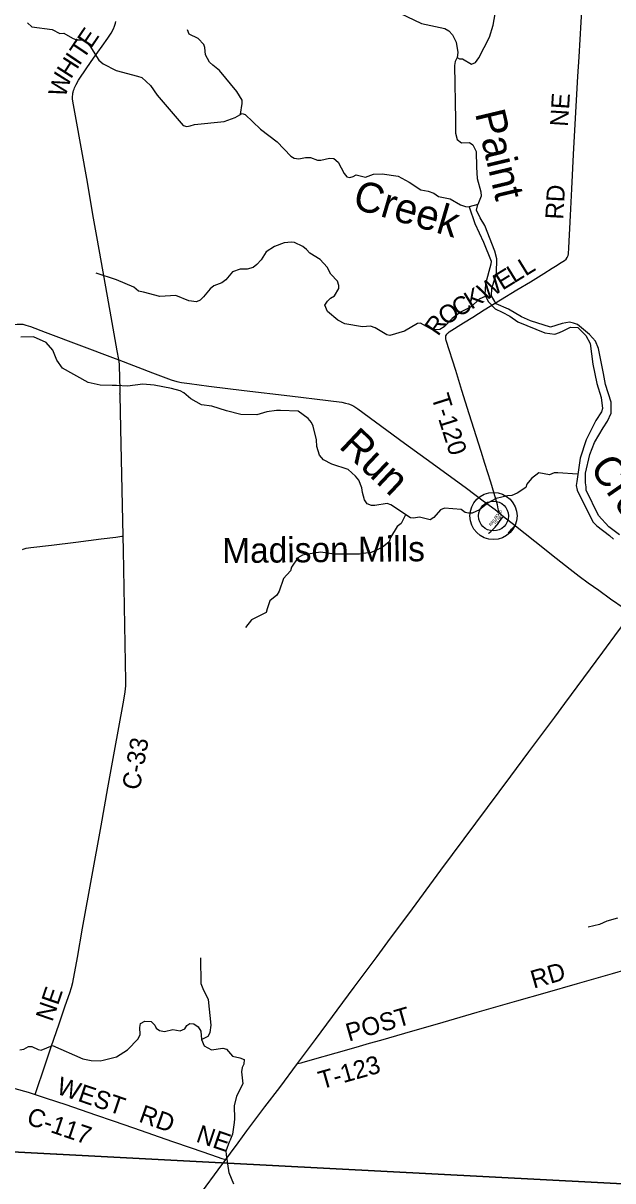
# Model space of a CAD drawing. Extents: x -51392 to 1635000, y 156707 to 696232.
# Drawn here: x 159089 to 168915, y 518358 to 537660 of the extents above; entities that cross this region are included whole.
import ezdxf

# ---------------------------------------------------------------- set-up
doc = ezdxf.new("R2010")
doc.units = 0
for name, color, linetype in [('GM_X_County_Road', 7, 'Continuous'), ('GM_X_County_Road_Text', 7, 'Continuous'), ('GM_X_Major_River', 7, 'Continuous'), ('GM_X_Major_River_Text', 7, 'Continuous'), ('GM_X_Minor_River', 7, 'Continuous'), ('GM_X_Minor_River_Text', 7, 'Continuous'), ('GM_X_Township', 7, 'Continuous'), ('GM_X_Township_Road', 7, 'Continuous'), ('GM_X_Township_Road_Text', 7, 'Continuous'), ('GM_X_Township_Subdivision', 7, 'Continuous'), ('GM_X_Township_Subdivision_Text', 7, 'Continuous'), ('GM_X_Unincorporated', 7, 'Continuous'), ('GM_X_Unincorporated_Text', 7, 'Continuous'), ('GM_X_US_Route', 7, 'Continuous')]:
    doc.layers.add(name, color=color, linetype=linetype)

msp = doc.modelspace()

# ---------------------------------------------------------------- linework, layer by layer
at = {"layer": 'GM_X_County_Road'}
for points in [[(160682, 532047), (160681, 532052), (160656, 532197), (160555, 532762), (160394, 533667), (160318, 534101), (160264, 534408), (160148, 535071), (159973, 536056), (159928, 536298), (159914, 536394), (159912, 536421), (159913, 536442), (159915, 536468), (159919, 536491), (159923, 536512), (159930, 536536), (159938, 536560), (159946, 536582), (159973, 536639), (160014, 536710), (160150, 536915), (160261, 537077), (160407, 537275), (160503, 537409), (160555, 537492), (160594, 537565), (160613, 537611), (160627, 537659), (160634, 537688)], [(157127, 532309), (157134, 532307), (157143, 532304), (157152, 532303), (157159, 532302), (157167, 532302), (157184, 532304), (157265, 532318), (157942, 532448), (158360, 532530), (158795, 532615), (158924, 532637), (158989, 532643), (159038, 532643), (159084, 532639), (159134, 532627), (159211, 532603), (159457, 532510), (160623, 532069), (160682, 532047)], [(160682, 532047), (161246, 531830), (161554, 531715), (161648, 531686), (161728, 531668), (161859, 531650), (162184, 531610), (162770, 531538), (163535, 531444), (164171, 531368), (164398, 531339), (164462, 531327), (164509, 531313), (164554, 531295), (164597, 531272), (164665, 531228), (165446, 530656), (165804, 530395), (166453, 529921), (166637, 529785), (166756, 529697), (166952, 529551), (167020, 529497)], [(160754, 529107), (160717, 530904), (160706, 531462), (160701, 531478), (160705, 531495), (160704, 531544), (160694, 531954), (160692, 531977), (160688, 532011), (160682, 532047)], [(167020, 529497), (167095, 529437)], [(167095, 529437), (167287, 529285)], [(167287, 529285), (167296, 529278), (167614, 529025), (167969, 528741), (168202, 528558), (168356, 528437), (168505, 528327), (168680, 528204), (168878, 528064), (169102, 527908), (169195, 527844), (169227, 527821)], [(159077, 528882), (159092, 528890), (159107, 528896), (159122, 528901), (159138, 528904), (159219, 528915), (159561, 528958), (159968, 529008), (160180, 529035), (160391, 529062), (160636, 529092), (160733, 529104), (160754, 529107)], [(159289, 519797), (159462, 520310), (159557, 520590), (159690, 520978), (159790, 521273), (159867, 521490), (159897, 521584), (159916, 521664), (159992, 522084), (160078, 522568), (160389, 524279), (160502, 524909), (160613, 525523), (160758, 526313), (160790, 526508), (160797, 526567), (160800, 526606), (160802, 526639), (160802, 526688), (160783, 527623), (160759, 528870), (160754, 529107)], [(157098, 519161), (157124, 519184), (157163, 519213), (157216, 519251), (157490, 519431), (157930, 519717), (158190, 519888), (158314, 519968), (158356, 519993), (158386, 520006), (158416, 520017), (158432, 520021), (158447, 520023), (158463, 520025), (158479, 520026), (158495, 520025), (158527, 520021), (158575, 520010), (158701, 519975), (158764, 519956), (158952, 519899), (159172, 519834), (159289, 519797)], [(159289, 519797), (159472, 519737), (159798, 519628), (160294, 519460), (160590, 519361), (160930, 519243), (161579, 519016), (161889, 518910), (162229, 518791), (162400, 518733), (162469, 518713)]]:
    msp.add_lwpolyline(points, dxfattribs=at)
at = {"layer": 'GM_X_Major_River'}
msp.add_line((166666, 534635), (166524, 534599), dxfattribs=at)
for points in [[(166320, 537089), (166361, 537065), (166411, 537067), (166559, 536979), (166627, 537007), (166683, 537083), (166862, 537424), (166924, 537625), (166981, 537970), (167129, 538419), (167129, 538501), (167079, 538678), (167029, 538810), (166997, 538983), (166955, 539631), (166957, 539697), (166958, 539996), (167046, 540558), (167107, 541279), (167185, 541590), (167233, 541794), (167287, 541921), (167466, 542164), (167534, 542314)], [(166320, 537089), (166286, 537019), (166278, 536957), (166296, 536042), (166292, 535825), (166320, 535721), (166392, 535663), (166526, 535668), (166583, 535630), (166637, 535522), (166643, 535261), (166652, 535071), (166715, 534850), (166721, 534776), (166666, 534635)], [(166524, 534599), (166616, 534320), (166762, 534011), (166886, 533692), (166884, 533640), (166792, 533315), (166782, 533137), (166838, 533020), (166956, 532898), (167073, 532840), (167197, 532777), (167331, 532681), (167784, 532498), (167951, 532476), (168027, 532504), (168089, 532530), (168210, 532590), (168332, 532586), (168466, 532454), (168538, 532317), (168584, 531972), (168648, 531653), (168722, 531420), (168742, 531234), (168728, 531180), (168630, 531037), (168471, 530712), (168371, 530406), (168313, 530016), (168303, 529950), (168321, 529874), (168583, 529348), (168651, 529278), (168858, 529120), (168924, 529055)], [(169026, 529129), (168848, 529260), (168679, 529453), (168469, 529872), (168471, 529932), (168461, 529998), (168459, 530155), (168535, 530468), (168608, 530666), (168754, 530915), (168829, 531025), (168887, 531156), (168889, 531340), (168793, 531637), (168759, 531820), (168679, 532235), (168627, 532357), (168524, 532470), (168328, 532636), (168260, 532660), (168194, 532673), (168071, 532655), (167877, 532592), (167542, 532699), (167395, 532761), (167179, 532890), (166970, 532982), (166892, 533116), (166898, 533237), (166979, 533490), (166981, 533730), (166951, 533861), (166784, 534284), (166702, 534413), (166644, 534541), (166666, 534635)]]:
    msp.add_lwpolyline(points, dxfattribs=at)
at = {"layer": 'GM_X_Minor_River'}
for points in [[(165366, 537828), (165729, 537655), (166114, 537569), (166182, 537535), (166244, 537468), (166305, 537342), (166331, 537169), (166320, 537089)], [(159163, 537664), (159233, 537600), (159572, 537552), (159700, 537487), (159767, 537491), (159909, 537409), (159979, 537385), (160081, 537381), (160136, 537351), (160200, 537285), (160348, 537042), (160420, 536984), (160641, 536873), (160996, 536777), (161066, 536752), (161214, 536622), (161324, 536459), (161753, 535956), (161814, 535938), (161872, 535948), (161944, 535972), (162439, 536019), (162624, 536090), (162738, 536154), (162790, 536136), (163045, 535895), (163320, 535684), (163550, 535445), (163606, 535411), (163682, 535397), (163795, 535421), (163877, 535421), (163995, 535375), (164051, 535375), (164192, 535411), (164266, 535403), (164338, 535344), (164436, 535154), (164482, 535096), (164535, 535086), (164589, 535102), (164641, 535132), (164793, 535093), (164930, 535142), (165074, 535150), (165341, 535107), (165523, 535007), (165714, 534880), (165838, 534860), (165934, 534826), (166011, 534768), (166207, 534734), (166379, 534633), (166458, 534601), (166524, 534599)], [(162712, 536142), (162740, 536320), (162736, 536374), (162652, 536521), (162359, 536870), (162251, 536961), (162195, 537009), (162127, 537131), (162119, 537252), (162099, 537304), (162005, 537402), (161856, 537476), (161828, 537547)], [(166797, 533110), (166686, 533060), (166555, 532930), (166377, 532844), (166238, 532736), (166104, 532599), (166032, 532553), (165913, 532545), (165711, 532656), (165659, 532654), (165442, 532527), (165199, 532451), (165149, 532461), (164955, 532580), (164878, 532606), (164742, 532598), (164449, 532648), (164333, 532710), (164161, 532853), (164119, 532959), (164159, 533027), (164213, 533074), (164277, 533116), (164347, 533234), (164351, 533286), (164325, 533358), (164219, 533475), (164155, 533591), (164041, 533718), (163866, 533828), (163810, 533884), (163748, 533936), (163612, 534003), (163559, 534011), (163441, 533995), (163275, 533935), (163140, 533850), (163054, 533712), (162982, 533638), (162924, 533586), (162821, 533558), (162705, 533558), (162577, 533514), (162464, 533381), (162400, 533329), (162268, 533279), (162205, 533231), (162093, 533099), (162037, 533043), (161975, 533016), (161848, 533031), (161634, 533117), (161365, 533101), (161092, 533173), (161010, 533193), (160936, 533256), (160647, 533378), (160306, 533491)], [(168328, 530138), (167998, 530165), (167936, 530163), (167861, 530131), (167685, 530165), (167559, 530067), (167484, 529975), (167464, 529919), (167320, 529822), (167230, 529782), (167159, 529780), (166973, 529732), (166836, 529664), (166694, 529544), (166574, 529488), (166513, 529488), (166455, 529504), (166387, 529550), (166112, 529572), (166042, 529548), (165932, 529420), (165874, 529378), (165693, 529424), (165593, 529406), (165543, 529414), (165214, 529631), (165154, 529653), (164947, 529619), (164893, 529619), (164821, 529645), (164779, 529713), (164745, 529834), (164733, 529910), (164681, 530040), (164629, 530109), (164506, 530219), (164232, 530305), (164095, 530382), (164029, 530456), (163985, 530600), (163977, 530711), (163921, 530941), (163895, 531002), (163839, 531068), (163672, 531190), (163380, 531200), (163311, 531200), (163149, 531182), (162981, 531132), (162714, 531133), (162475, 531195), (162235, 531275), (162062, 531297), (161882, 531398), (161769, 531498), (161703, 531532), (161561, 531570), (161270, 531627), (161082, 531639), (160827, 531609), (160644, 531617), (160570, 531619), (160372, 531625), (160175, 531671), (159744, 531906), (159652, 532039), (159584, 532207), (159471, 532334), (159263, 532430), (159048, 532424)], [(165459, 529462), (165388, 529318), (165320, 529270), (165210, 529083), (165188, 529013), (165069, 528915), (164887, 528835), (164833, 528827), (164696, 528805), (164271, 528807), (164044, 528841), (163802, 528801), (163746, 528789), (163667, 528745), (163559, 528591), (163545, 528530), (163428, 528402), (163358, 528189), (163318, 528121), (163198, 528027), (163158, 527893), (163137, 527835), (162893, 527710), (162792, 527586)], [(168995, 522739), (168813, 522685), (168694, 522630), (168506, 522588)], [(162061, 520714), (162172, 520768), (162206, 520832), (162222, 520955), (162178, 521380), (162100, 521529), (162056, 521645), (162048, 522074)], [(159033, 520543), (159101, 520553), (159177, 520597), (159231, 520599), (159340, 520545), (159392, 520539), (159576, 520613), (160084, 520390), (160224, 520362), (160372, 520360), (160423, 520370), (160643, 520424), (160828, 520544), (161004, 520725), (161038, 520795), (161032, 520913), (161047, 520983), (161117, 521020), (161223, 521013), (161285, 520953), (161305, 520901), (161361, 520863), (161442, 520847), (161586, 520883), (161708, 520859), (161783, 520893), (161815, 520947), (161869, 520979), (161931, 520973), (162003, 520923), (162051, 520855), (162061, 520714), (162105, 520610), (162228, 520544), (162414, 520570), (162480, 520553), (162576, 520439), (162699, 520409), (162771, 520379), (162769, 520305), (162739, 520248), (162729, 520178), (162749, 519974), (162642, 519769), (162608, 519611), (162610, 519394), (162604, 519328), (162576, 519135), (162535, 519027)], [(162598, 518303), (162524, 518494), (162478, 518792), (162472, 518860), (162535, 519027)]]:
    msp.add_lwpolyline(points, dxfattribs=at)
at = {"layer": 'GM_X_Township'}
for points in [[(177580, 517864), (162392, 518660), (156896, 518947), (156648, 518960), (156580, 519550), (155872, 525660), (155251, 531033), (154449, 537962), (154393, 538443), (153721, 544251), (153416, 546885), (154887, 546778), (157022, 546663), (159649, 546538), (163080, 546381), (166694, 546239), (167692, 546175), (177006, 545575)], [(156029, 512335), (156615, 518610), (156648, 518960), (156896, 518947), (162392, 518660), (177580, 517864)]]:
    msp.add_lwpolyline(points, dxfattribs=at)
at = {"layer": 'GM_X_Township_Road'}
for points in [[(167020, 529497), (167005, 529563), (166991, 529627), (166938, 529816), (166881, 530005), (166784, 530318), (166721, 530521), (166524, 531147), (166399, 531538), (166297, 531867), (166140, 532367), (166133, 532399), (166131, 532415), (166132, 532430), (166135, 532446), (166141, 532462), (166152, 532479), (166165, 532493), (166190, 532514), (166427, 532661), (166580, 532757), (166774, 532879), (167318, 533213), (167543, 533349), (167766, 533487), (167905, 533574), (167959, 533611), (168057, 533669), (168112, 533705), (168136, 533727), (168155, 533754), (168169, 533784), (168175, 533816), (168183, 533914), (168209, 534455), (168230, 534897), (168260, 535470), (168286, 535978), (168330, 536773), (168352, 537098), (168406, 537966)], [(163661, 520313), (163723, 520328), (163739, 520332), (163913, 520380), (164307, 520494), (164638, 520588), (164858, 520651), (165047, 520706), (165583, 520860), (165993, 520977), (166370, 521088), (166654, 521168), (167317, 521357), (167790, 521492), (168325, 521648), (168908, 521815), (169365, 521947)]]:
    msp.add_lwpolyline(points, dxfattribs=at)
at = {"layer": 'GM_X_Township_Subdivision'}
for points in [[(166842, 529153), (166854, 529164), (166880, 529187), (166929, 529227), (166957, 529255), (166979, 529284), (166991, 529302), (167038, 529369), (167079, 529419), (167095, 529437)], [(167177, 529167), (167208, 529203), (167226, 529223), (167245, 529242), (167265, 529263), (167287, 529285)], [(167173, 529163), (167177, 529167)]]:
    msp.add_lwpolyline(points, dxfattribs=at)
at = {"layer": 'GM_X_Unincorporated'}
for radius in [393, 249]:
    msp.add_circle((166926, 529443), radius, dxfattribs=at)
at = {"layer": 'GM_X_US_Route'}
for points in [[(168750, 527175), (169011, 527528), (169148, 527712), (169227, 527821), (169245, 527845), (169350, 527991), (169553, 528270), (169784, 528588), (170015, 528907), (170150, 529093)], [(162075, 518186), (162340, 518539), (162469, 518713), (162544, 518820), (162670, 518994), (162819, 519190), (163119, 519593), (163364, 519912), (163661, 520313), (163960, 520716), (164605, 521585), (164987, 522099), (165211, 522403), (165514, 522811), (166051, 523535), (167214, 525103), (167517, 525511), (167948, 526090), (168113, 526315), (168748, 527172), (168750, 527175)]]:
    msp.add_lwpolyline(points, dxfattribs=at)

# ---------------------------------------------------------------- texts
at = {"layer": 'GM_X_County_Road_Text'}
for s, rotation, p in [('E', 56.0602, (160220, 537228)), ('T', 56.0521, (160095, 537042)), ('H', 57.2971, (159884, 536719)), ('I', 56.108, (160026, 536940)), ('W', 72.5489, (159789, 536407)), ('C-33', 79.835, (161029, 524861)), ('NE', 70.9575, (159574, 520998)), ('WEST', 341.2245, (159626, 519816)), ('C-117', 341.1443, (159129, 519309)), ('RD', 340.6723, (161000, 519349)), ('NE', 341.1276, (161953, 519015))]:
    msp.add_text(s, height=300, rotation=rotation, dxfattribs=at).set_placement(p)
at = {"layer": 'GM_X_Major_River_Text'}
for s, rotation, p in [('Paint', 283.3881, (166617, 536159)), ('Creek', 304.7049, (168518, 530250))]:
    msp.add_text(s, height=500, rotation=rotation, dxfattribs=at).set_placement(p)
at = {"layer": 'GM_X_Minor_River_Text'}
for s, rotation, p in [('Creek', 343.7059, (164558, 534581)), ('Run', 316.7055, (164334, 530591))]:
    msp.add_text(s, height=500, rotation=rotation, dxfattribs=at).set_placement(p)
at = {"layer": 'GM_X_Township_Road_Text'}
for s, rotation, p in [('NE', 86.4165, (168167, 535929)), ('RD', 86.9073, (168089, 534381)), ('L', 31.6818, (167459, 533434)), ('E', 31.6818, (167077, 533199)), ('L', 31.6794, (167268, 533317)), ('W', 31.6802, (166781, 533016)), ('K', 31.6797, (166557, 532878)), ('O', 31.8203, (166123, 532609)), ('C', 31.6817, (166347, 532748)), ('R', 54.7209, (166003, 532429)), ('T-120', 287.6396, (165888, 531428)), ('RD', 16.2334, (167596, 521561)), ('POST', 15.9888, (164516, 520678)), ('T-123', 15.8679, (164059, 519882))]:
    msp.add_text(s, height=300, rotation=rotation, dxfattribs=at).set_placement(p)
at = {"layer": 'GM_X_Township_Subdivision_Text'}
for s, rotation, p in [('O', 53.2271, (166993, 529415)), ('A', 47.0533, (167018, 529449)), ('D', 45.5385, (167048, 529481)), ('R', 53.2364, (166885, 529270)), ('A', 53.2271, (166909, 529302)), ('I', 53.1965, (166935, 529337)), ('L', 53.2391, (166948, 529355)), ('R', 53.247, (166969, 529383)), ('S', 54.3625, (166977, 529293)), ('T', 54.3743, (166997, 529322)), ('N', 53.1659, (167025, 529361)), ('E', 49.3269, (167051, 529396))]:
    msp.add_text(s, height=50, rotation=rotation, dxfattribs=at).set_placement(p)
at = {"layer": 'GM_X_Unincorporated_Text'}
msp.add_text('Madison Mills', height=417, rotation=0.5386, dxfattribs=at).set_placement((162408, 528658))

doc.saveas('drawing.dxf')
